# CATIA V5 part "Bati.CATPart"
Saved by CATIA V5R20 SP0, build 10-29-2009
Part number: Bati
Bounding box of the stored display mesh (mm): x -8 to 0, y -8 to 91, z -8 to 65.669
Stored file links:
  D:\thinkmotion-MPB\Dropbox\IAO_2012\IAO_2012_753_jrecappe\jrecappe.zip\Bati.CATPart
  D:\thinkmotion-MPB\Dropbox\IAO_2012\IAO_2012_753_jrecappe\jrecappe.zip\Ass_skl_levier2bras.CATProduct
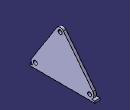
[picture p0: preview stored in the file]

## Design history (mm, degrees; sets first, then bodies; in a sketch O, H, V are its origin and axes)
Set1
  Point1 "Point G": linked copy from another document
  DatumPoint1 "Point D": linked copy from another document
  Point2 "Point A": linked copy from another document
Body1 (main body)
  Sketch1 on yz-plane, origin (0, 0, 0), H (0, 1, 0), V (0, 0, 1)
    point P1 (0, -6.2105)
    line L1 (0, -6.2105) -> (80.9338, -6.2105)
    line L2 (88, 6) -> (43.076, 63.2687)
    arc A1 centre (38.1377, 59.3949) radius 6.2764 from (43.076, 63.2687) to (33, 63) ccw
    line L3 (33, 63) -> (-6, 2)
    point P7 (-6, 2)
    arc A2 centre (0, 0.087) radius 6.2976 from (-6, 2) to (0, -6.2105) ccw
    point P9 (-6, 2)
    arc A3 centre (82.0213, 1.31) radius 7.5988 from (80.9338, -6.2105) to (88, 6) ccw
    circle A4 centre (83.1, 0) radius 3
    point P11 (83.1, 0)
    reference projected point E1 (83.1, 0) from Point1
    circle A5 centre (38.1498, 59.2861) radius 3
    point P12 (38.1498, 59.2861)
    reference projected point E2 (38.1498, 59.2861) from DatumPoint1
    circle A6 centre (0, 0) radius 3
    point P13 (0, 0)
    reference projected point E3 (0, 0) from Point2
    coincidence: P1 V, P9 L3, P7 P9, P11 E1, P12 E2, P13 E3
    horizontal: L1 H
    tangency: A1 L2, A2 L1, A3 L2
  Pad1: profile Sketch1, direction (-1, 0, 0), length 4
  Sketch2 on xy-plane, origin (0, 0, 0), H (1, 0, 0), V (0, 1, 0)
    line L1 (0, -8) -> (-8, -8)
    line L2 (-8, -8) -> (-8, 91)
    line L3 (-8, 91) -> (0, 91)
    line L4 (0, -8) -> (0, 91)
    point P3 (0, -8)
    horizontal: L1 H, L3 H
    vertical: L2 V, L4 V
    coincidence: P3 L1, P3 V, P3 L4
  Pad2: profile Sketch2, direction (0, 0, 1), length -8, opposite side length 5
